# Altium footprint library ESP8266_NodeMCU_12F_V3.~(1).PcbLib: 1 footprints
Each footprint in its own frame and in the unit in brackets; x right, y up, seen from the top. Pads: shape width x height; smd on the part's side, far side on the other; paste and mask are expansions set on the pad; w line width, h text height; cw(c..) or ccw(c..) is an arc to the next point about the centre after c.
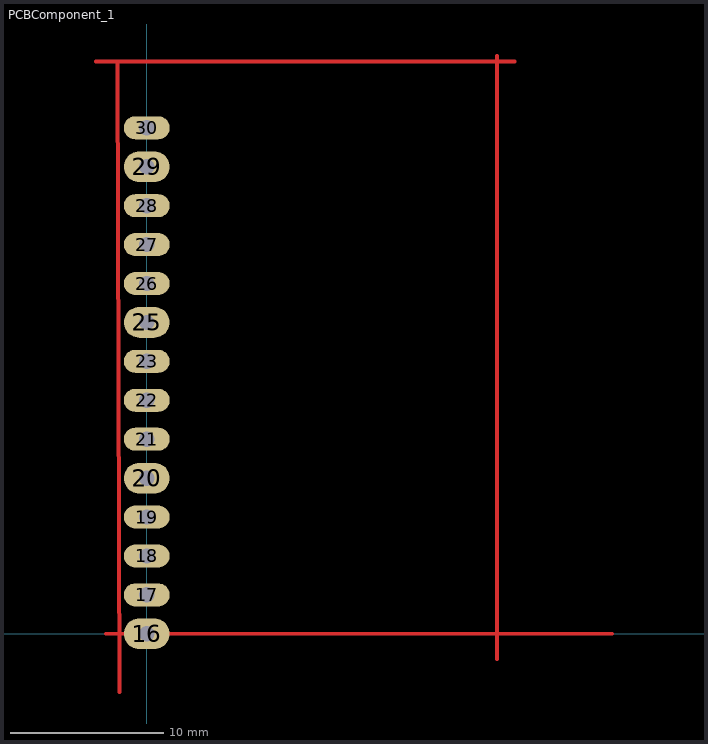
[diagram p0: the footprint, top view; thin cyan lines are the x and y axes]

## PCBComponent_1 [mm]
pads (14):
  oval 3x2 hole 1 paste+0 mask+0.102: 16(0,0) 20(0,10.16) 25(0,20.32) 29(0,30.48)
  oval 3x1.5 hole 1 paste+0 mask+0.102: 17(0,2.54) 18(0,5.08) 19(0,7.62) 21(0,12.7) 22(0,15.24) 23(0,17.78) 26(0,22.86) 27(0,25.4) 28(0,27.94) 30(0,33.02)
Top Layer:
  lines w0.254: -3.302,37.338 24.003,37.338 ; -2.667,0 30.353,0 ; -1.905,37.211 -1.778,-3.81 ; 22.86,-1.651 22.86,37.719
